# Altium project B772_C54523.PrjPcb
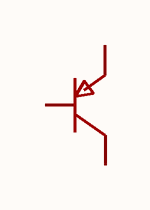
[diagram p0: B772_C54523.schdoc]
1 sheet, 1 parts. Net scope: global (net labels, ports and power ports of the same name join across sheets).

## Sheet B772_C54523.schdoc
size 127 x 101 mm

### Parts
Q?  b772(range:160-320)  [TO-126-3_L7.6-W2.7-P2.30-L]  (value not drawn)

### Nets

Not connected (* = marked no-connect by the designer): Q? 1(E) 2(C) 3(B)

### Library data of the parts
Q? = b772(range:160-320): 晶体管类型:PNP;集电极电流(Ic):3A;集射极击穿电压(Vceo):30V;耗散功率(Pd):1.25W;直流电流增益(hFE):60;; Manufacturer: CJ(江苏长电/长晶); Symbol: B772_C54523; AddInBom: yes; ModelId: 7e16fa0fc5b945c899301d14551435f6; ModelTransform: 299.212,106.6927,0,0,0,0,0,7.992,-196.85; type: PNP; Current - Collector(Ic): 3A; Collector - Emitter Voltage VCEO: 30V; Pd - Power Dissipation: 1.25W; DC Current Gain: 60; Transition frequency(fT): 50MHz; Current - Collector Cutoff: 1uA; Vce Saturation(VCE(sat)): 500mV; Emitter-Base Voltage(Vebo): 6V; Number: 1个PNP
